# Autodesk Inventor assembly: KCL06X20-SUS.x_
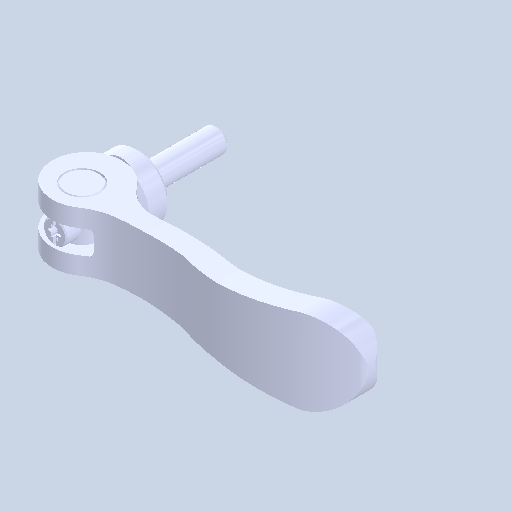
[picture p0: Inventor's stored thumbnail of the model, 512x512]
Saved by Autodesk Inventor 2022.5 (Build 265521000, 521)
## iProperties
Created: 2024-08
Part Number: KCL06X20-SUS.x_
Document SubType Name: Assembly
Designer: ImaoCorp
Author: ImaoCorp
Sending System: SOLIDWORKS 2022-2022290
MC: AMD64
MC_MODEL: Intel64 Family 6 Model 60 Stepping 3, GenuineIntel
OS: Windows_NT
FRU: Parasolid Version 33.1, build 260,  4-25-2022
FORMAT: text
GUISE: transmit
KEY: FILEKCL06X20-SUS.x_t
DATE: Thu Aug 29 10:49:41 2024
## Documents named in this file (5)
- Y:\5.更新分\2024年対応\1001_KCL\データ\kcl06x20-sus\KCL06X20-SUS.x_.iam
- Y:\5.更新分\2024年対応\1001_KCL\データ\kcl06x20-sus\KCL06X20-SUS_01.ipt
- Y:\5.更新分\2024年対応\1001_KCL\データ\kcl06x20-sus\KCL06X20-SUS_02.ipt
- Y:\5.更新分\2024年対応\1001_KCL\データ\kcl06x20-sus\KCL06X20-SUS_03.ipt
- Y:\5.更新分\2024年対応\1001_KCL\データ\kcl06x20-sus\KCL06X20-SUS_04.ipt
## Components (4 placed, 4 different names)
1. KCL06X20-SUS_01
2. KCL06X20-SUS_02
3. KCL06X20-SUS_03
4. KCL06X20-SUS_04
